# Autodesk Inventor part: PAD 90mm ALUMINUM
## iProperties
Created: 2007-03
Part Number: PAD 90mm ALUMINUM
Document SubType Name: Modeling
Designer: Andy Moles
Material: Aluminum-6061
Mass: 168.965 g
Surface Area: 171.641 cm^2
Volume: 62.3487 cm^3
Density: 2.71 g/cm^3
Author: Andy Moles
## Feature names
1. Revolution1
